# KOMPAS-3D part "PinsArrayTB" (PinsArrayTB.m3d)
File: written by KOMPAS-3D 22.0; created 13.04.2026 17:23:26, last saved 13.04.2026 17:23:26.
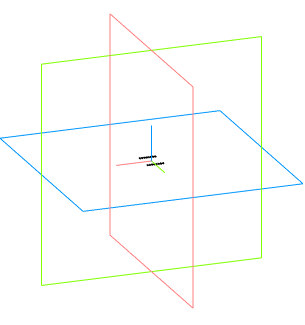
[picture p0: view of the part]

Document properties: Автор: Andrey; Полное имя файла: C:\Users\User1\Documents\PinsArrayTB.m3d

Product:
- Part/product: PinsArrayTB

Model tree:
1. Операция без истории:1
2. Операция без истории:2
3. Операция без истории:3
4. Операция без истории:4
5. Операция без истории:5
6. Операция без истории:6
7. Операция без истории:7
8. Операция без истории:8
9. Операция без истории:9
10. Операция без истории:10
11. Операция без истории:11
12. Операция без истории:12
13. Операция без истории:13
14. Операция без истории:14
15. Операция без истории:15
16. Операция без истории:16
